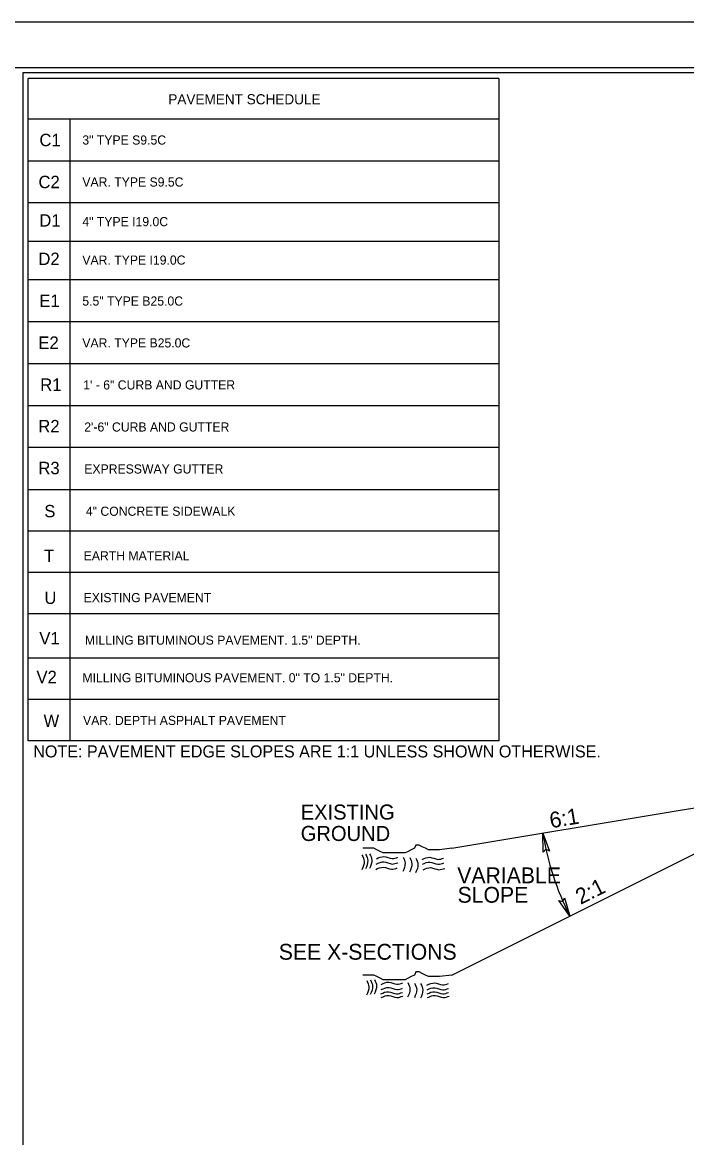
# Model space of a CAD drawing. Extents: x 2294370 to 2294957, y 719276 to 719941.
# Drawn here: x 2294488.5 to 2294554, y 719386.3 to 719496.3 of the extents above; entities that cross this region are included whole.
import ezdxf

# ---------------------------------------------------------------- set-up
doc = ezdxf.new("R2010")
doc.units = 0
for name, color, linetype in [('Old_Level_1', 7, 'Continuous'), ('Old_Level_11', 7, 'Continuous'), ('Old_Level_2', 7, 'Continuous'), ('Prop Dimension Text', 7, 'Continuous'), ('Prop Pavement Schedule Description CELL', 7, 'Continuous'), ('Sheet Cutting Line CELL', 7, 'Continuous'), ('Sheet Plot Border Inside CELL', 7, 'Continuous'), ('Sheet Plot Border Outside CELL', 7, 'Continuous'), ('Sheet Typical CELL', 7, 'Continuous'), ('Typical Hinge Slope Arterial CELL', 7, 'Continuous')]:
    doc.layers.add(name, color=color, linetype=linetype)

msp = doc.modelspace()

# ---------------------------------------------------------------- linework, layer by layer
at = {"layer": 'Old_Level_11'}
for points in [[(2294539.83, 719414.5), (2294539.79, 719416.37), (2294540.46, 719414.61), (2294540.1, 719414.78)], [(2294541.95, 719409.98), (2294542.45, 719408.18), (2294541.37, 719409.72), (2294541.76, 719409.64)]]:
    msp.add_lwpolyline(points, close=True, dxfattribs=at)
at = {"layer": 'Old_Level_2'}
for points in [[(2294522.73, 719414.33), (2294522.95, 719413.71), (2294522.72, 719412.89)], [(2294522.73, 719414.33), (2294522.95, 719413.71), (2294522.72, 719412.89)], [(2294521.98, 719414.22), (2294522.19, 719413.6), (2294521.96, 719412.77)], [(2294521.98, 719414.22), (2294522.19, 719413.6), (2294521.96, 719412.77)], [(2294522.34, 719414.29), (2294522.55, 719413.67), (2294522.32, 719412.84)], [(2294522.34, 719414.29), (2294522.55, 719413.67), (2294522.32, 719412.84)], [(2294523.39, 719413.32), (2294524.15, 719413.54), (2294524.94, 719413.33), (2294525.51, 719413.46)], [(2294523.39, 719413.32), (2294524.15, 719413.54), (2294524.94, 719413.33), (2294525.51, 719413.46)], [(2294523.4, 719413.85), (2294524.15, 719414.06), (2294524.94, 719413.86), (2294525.51, 719413.99)], [(2294523.4, 719413.85), (2294524.15, 719414.06), (2294524.94, 719413.86), (2294525.51, 719413.99)], [(2294526.03, 719414.02), (2294526.23, 719413.4), (2294526.01, 719412.58)], [(2294526.03, 719414.02), (2294526.23, 719413.4), (2294526.01, 719412.58)], [(2294526.68, 719413.97), (2294526.89, 719413.35), (2294526.67, 719412.53)], [(2294526.68, 719413.97), (2294526.89, 719413.35), (2294526.67, 719412.53)], [(2294527.29, 719413.92), (2294527.5, 719413.3), (2294527.27, 719412.47)], [(2294527.29, 719413.92), (2294527.5, 719413.3), (2294527.27, 719412.47)], [(2294527.91, 719413.77), (2294528.66, 719413.99), (2294529.45, 719413.79), (2294530.03, 719413.91)], [(2294527.91, 719413.77), (2294528.66, 719413.99), (2294529.45, 719413.79), (2294530.03, 719413.91)], [(2294527.93, 719413.3), (2294528.68, 719413.52), (2294529.47, 719413.31), (2294530.05, 719413.44)], [(2294527.93, 719413.3), (2294528.68, 719413.52), (2294529.47, 719413.31), (2294530.05, 719413.44)], [(2294523.33, 719412.79), (2294524.09, 719413.01), (2294524.88, 719412.81), (2294525.46, 719412.94)], [(2294523.33, 719412.79), (2294524.09, 719413.01), (2294524.88, 719412.81), (2294525.46, 719412.94)], [(2294528.01, 719412.76), (2294528.76, 719412.97), (2294529.55, 719412.77), (2294530.13, 719412.9)], [(2294528.01, 719412.76), (2294528.76, 719412.97), (2294529.55, 719412.77), (2294530.13, 719412.9)], [(2294522.45, 719401.83), (2294522.66, 719401.21), (2294522.43, 719400.39)], [(2294522.45, 719401.83), (2294522.66, 719401.21), (2294522.43, 719400.39)], [(2294522.82, 719401.9), (2294523.03, 719401.28), (2294522.8, 719400.46)], [(2294522.82, 719401.9), (2294523.03, 719401.28), (2294522.8, 719400.46)], [(2294523.21, 719401.94), (2294523.42, 719401.32), (2294523.19, 719400.5)], [(2294523.21, 719401.94), (2294523.42, 719401.32), (2294523.19, 719400.5)], [(2294523.87, 719401.46), (2294524.62, 719401.68), (2294525.42, 719401.47), (2294525.99, 719401.6)], [(2294523.87, 719401.46), (2294524.62, 719401.68), (2294525.42, 719401.47), (2294525.99, 719401.6)], [(2294523.87, 719400.94), (2294524.62, 719401.15), (2294525.41, 719400.95), (2294525.98, 719401.08)], [(2294523.87, 719400.94), (2294524.62, 719401.15), (2294525.41, 719400.95), (2294525.98, 719401.08)], [(2294526.5, 719401.64), (2294526.71, 719401.02), (2294526.48, 719400.19)], [(2294526.5, 719401.64), (2294526.71, 719401.02), (2294526.48, 719400.19)], [(2294527.15, 719401.59), (2294527.37, 719400.96), (2294527.14, 719400.14)], [(2294527.15, 719401.59), (2294527.37, 719400.96), (2294527.14, 719400.14)], [(2294527.76, 719401.53), (2294527.97, 719400.91), (2294527.74, 719400.09)], [(2294527.76, 719401.53), (2294527.97, 719400.91), (2294527.74, 719400.09)], [(2294528.38, 719401.39), (2294529.14, 719401.6), (2294529.93, 719401.4), (2294530.5, 719401.53)], [(2294528.38, 719401.39), (2294529.14, 719401.6), (2294529.93, 719401.4), (2294530.5, 719401.53)], [(2294528.4, 719400.92), (2294529.16, 719401.13), (2294529.95, 719400.93), (2294530.52, 719401.06)], [(2294528.4, 719400.92), (2294529.16, 719401.13), (2294529.95, 719400.93), (2294530.52, 719401.06)], [(2294523.84, 719400.52), (2294524.59, 719400.73), (2294525.39, 719400.53), (2294525.96, 719400.66)], [(2294523.84, 719400.52), (2294524.59, 719400.73), (2294525.39, 719400.53), (2294525.96, 719400.66)], [(2294523.88, 719400.16), (2294524.63, 719400.37), (2294525.43, 719400.17), (2294526, 719400.3)], [(2294528.4, 719400.52), (2294529.16, 719400.73), (2294529.95, 719400.53), (2294530.52, 719400.66)], [(2294528.4, 719400.52), (2294529.16, 719400.73), (2294529.95, 719400.53), (2294530.52, 719400.66)], [(2294528.44, 719400.16), (2294529.2, 719400.37), (2294529.99, 719400.17), (2294530.57, 719400.3)]]:
    msp.add_spline(points, degree=3, dxfattribs=at)
at = {"layer": 'Prop Pavement Schedule Description CELL'}
for p, q in [((2294535.47, 719490.8), (2294489.08, 719490.8)), ((2294489.08, 719425.47), (2294489.08, 719490.8)), ((2294535.47, 719490.8), (2294535.47, 719425.47)), ((2294535.47, 719486.8), (2294489.08, 719486.8)), ((2294493.22, 719425.47), (2294493.22, 719486.8)), ((2294535.47, 719482.66), (2294489.08, 719482.66)), ((2294530.85, 719478.53), (2294489.08, 719478.53)), ((2294535.47, 719478.53), (2294489.08, 719478.53)), ((2294535.47, 719474.73), (2294489.08, 719474.73)), ((2294530.85, 719470.94), (2294489.08, 719470.94)), ((2294535.47, 719470.94), (2294489.08, 719470.94)), ((2294530.85, 719466.81), (2294489.08, 719466.81)), ((2294535.47, 719466.81), (2294489.08, 719466.81)), ((2294530.85, 719462.67), (2294489.08, 719462.67)), ((2294535.47, 719462.67), (2294489.08, 719462.67)), ((2294535.47, 719458.53), (2294489.08, 719458.53)), ((2294535.47, 719454.39), (2294489.08, 719454.39)), ((2294530.85, 719450.23), (2294489.08, 719450.23)), ((2294535.47, 719450.23), (2294489.08, 719450.23)), ((2294535.47, 719446.16), (2294489.08, 719446.16)), ((2294535.47, 719442.08), (2294489.08, 719442.08)), ((2294535.47, 719438), (2294489.08, 719438)), ((2294535.47, 719433.62), (2294489.08, 719433.62)), ((2294535.47, 719429.54), (2294489.08, 719429.54)), ((2294535.47, 719425.47), (2294489.08, 719425.47))]:
    msp.add_line(p, q, dxfattribs=at)
at = {"layer": 'Sheet Cutting Line CELL'}
msp.add_line((2294791.96, 719496.34), (2294455.16, 719496.34), dxfattribs=at)
at = {"layer": 'Sheet Plot Border Inside CELL'}
msp.add_lwpolyline([(2294791.06, 719491.85), (2294457.76, 719491.85), (2294457.76, 719280.83), (2294791.06, 719280.83)], close=True, dxfattribs=at)
at = {"layer": 'Sheet Plot Border Outside CELL'}
for points in [[(2294455.16, 719276.34), (2294791.96, 719276.34), (2294791.96, 719496.34), (2294455.16, 719496.34)], [(2294791.96, 719496.34), (2294455.16, 719496.34), (2294455.16, 719276.34), (2294791.96, 719276.34)]]:
    msp.add_lwpolyline(points, close=True, dxfattribs=at)
at = {"layer": 'Sheet Typical CELL'}
msp.add_lwpolyline([(2294788.56, 719491.34), (2294488.56, 719491.34), (2294488.56, 719281.34), (2294788.56, 719281.34)], close=True, dxfattribs=at)
at = {"layer": 'Typical Hinge Slope Arterial CELL'}
for p, q in [((2294530.84, 719402.38), (2294568.34, 719421.13)), ((2294553.34, 719418.63), (2294568.34, 719421.13)), ((2294530.84, 719414.88), (2294553.34, 719418.63))]:
    msp.add_line(p, q, dxfattribs=at)
for points in [[(2294530.84, 719414.88), (2294529.61, 719414.72), (2294529.31, 719414.72), (2294528.84, 719414.72), (2294528.53, 719414.72), (2294528.23, 719414.88), (2294527.92, 719415.03), (2294527.61, 719415.19), (2294527.3, 719415.19), (2294527.15, 719414.88), (2294526.84, 719414.72), (2294526.53, 719414.57), (2294526.22, 719414.42), (2294525.92, 719414.42), (2294525.61, 719414.42), (2294525.3, 719414.42), (2294524.99, 719414.42), (2294524.68, 719414.42), (2294524.38, 719414.42), (2294524.07, 719414.42), (2294523.76, 719414.57), (2294523.45, 719414.72), (2294523.14, 719414.88), (2294522.68, 719414.88), (2294522.37, 719414.88), (2294522.07, 719414.88)], [(2294530.84, 719402.38), (2294529.61, 719402.23), (2294529.31, 719402.23), (2294528.84, 719402.23), (2294528.53, 719402.23), (2294528.23, 719402.38), (2294527.92, 719402.53), (2294527.61, 719402.69), (2294527.3, 719402.69), (2294527.15, 719402.38), (2294526.84, 719402.23), (2294526.53, 719402.07), (2294526.22, 719401.92), (2294525.92, 719401.92), (2294525.61, 719401.92), (2294525.3, 719401.92), (2294524.99, 719401.92), (2294524.68, 719401.92), (2294524.38, 719401.92), (2294524.07, 719401.92), (2294523.76, 719402.07), (2294523.45, 719402.23), (2294523.14, 719402.38), (2294522.68, 719402.38), (2294522.37, 719402.38), (2294522.07, 719402.38)]]:
    msp.add_lwpolyline(points, dxfattribs=at)
msp.add_arc((2294568.34, 719421.13), 28.94, 189.4624, 206.5651, dxfattribs=at)

# ---------------------------------------------------------------- texts
at = {"layer": 'Old_Level_1'}
for s, height, rotation, p in [('EXISTING', 1.484, 360, (2294515.94, 719417.71)), ('6:1', 1.562, 9.4623, (2294540.6, 719416.85)), ('GROUND', 1.484, 360, (2294515.94, 719415.6)), ('2:1', 1.562, 26.5651, (2294543.52, 719409.29)), ('SEE X-SECTIONS', 1.5625, 360, (2294513.78, 719403.89))]:
    msp.add_text(s, height=height, rotation=rotation, dxfattribs=at).set_placement(p)
at = {"layer": 'Prop Dimension Text'}
msp.add_text('NOTE: PAVEMENT EDGE SLOPES ARE 1:1 UNLESS SHOWN OTHERWISE.', height=1.1875, dxfattribs=at).set_placement((2294489.58, 719423.84))
at = {"layer": 'Prop Pavement Schedule Description CELL'}
for s, height, p in [('C1', 1.225, (2294490.19, 719484.12)), ('3" TYPE S9.5C', 0.9, (2294494.42, 719484.28)), ('C2', 1.225, (2294490.1, 719479.98)), ('VAR. TYPE S9.5C', 0.9, (2294494.42, 719480.14)), ('D1', 1.225, (2294490.18, 719476.19)), ('4" TYPE I19.0C', 0.9, (2294494.42, 719476.23)), ('D2', 1.225, (2294490.09, 719472.4)), ('VAR. TYPE I19.0C', 0.9, (2294494.42, 719472.44)), ('E1', 1.225, (2294490.18, 719468.26)), ('5.5" TYPE B25.0C', 0.9, (2294494.42, 719468.4)), ('E2', 1.225, (2294490.09, 719464.13)), ('VAR. TYPE B25.0C', 0.9, (2294494.42, 719464.27)), ('R1', 1.225, (2294490.27, 719459.99)), ('1\' - 6" CURB AND GUTTER', 0.9, (2294494.51, 719460.13)), ('R2', 1.225, (2294490.08, 719455.9)), ('2\'-6" CURB AND GUTTER', 0.9, (2294494.61, 719455.98)), ('R3', 1.225, (2294490.09, 719451.77)), ('EXPRESSWAY GUTTER', 0.9, (2294494.61, 719451.84)), ('S', 1.22, (2294490.67, 719447.52)), ('4" CONCRETE SIDEWALK', 0.9, (2294494.77, 719447.67)), ('T', 1.22, (2294490.65, 719443.12)), ('EARTH MATERIAL', 0.9, (2294494.55, 719443.28)), ('U', 1.22, (2294490.68, 719438.98)), ('EXISTING PAVEMENT', 0.9, (2294494.55, 719439.15)), ('V1', 1.225, (2294490.18, 719434.98)), ('MILLING BITUMINOUS PAVEMENT. 1.5" DEPTH.', 0.9, (2294494.67, 719434.96)), ('V2', 1.225, (2294489.9, 719431.16)), ('MILLING BITUMINOUS PAVEMENT. 0" TO 1.5" DEPTH.', 0.9, (2294494.43, 719431.25)), ('W', 1.22, (2294490.6, 719426.85)), ('VAR. DEPTH ASPHALT PAVEMENT', 0.9, (2294494.49, 719427.04))]:
    msp.add_text(s, height=height, dxfattribs=at).set_placement(p)
at = {"layer": 'Sheet Typical CELL'}
msp.add_text('PAVEMENT SCHEDULE', height=1, rotation=360, dxfattribs=at).set_placement((2294502.89, 719488.25))
at = {"layer": 'Typical Hinge Slope Arterial CELL'}
for s, p in [('VARIABLE ', (2294531.37, 719411.43)), ('SLOPE', (2294531.4, 719409.51))]:
    msp.add_text(s, height=1.562, dxfattribs=at).set_placement(p)

doc.saveas('drawing.dxf')
